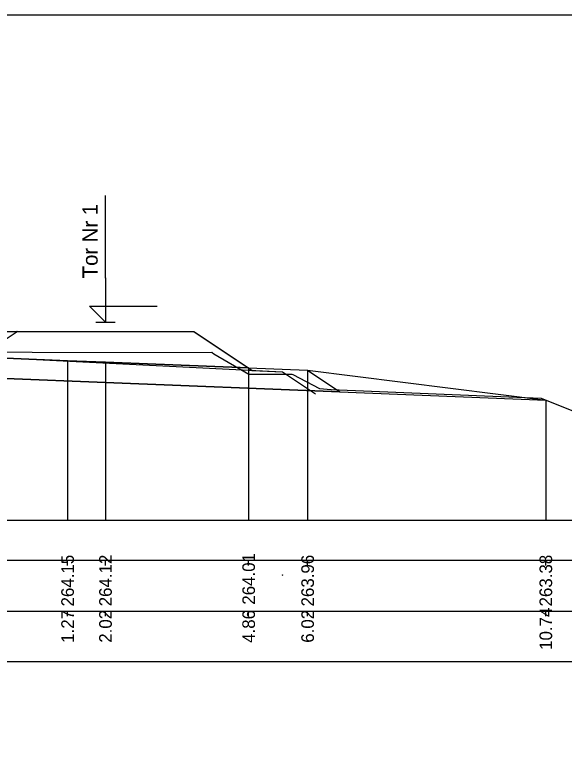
# Model space of a CAD drawing. Extents: x -1 to 65640748, y -22 to 5530284.
# Drawn here: x 2498.56 to 2509.43, y 1008.9 to 1023.44 of the extents above; entities that cross this region are included whole.
import ezdxf

# ---------------------------------------------------------------- set-up
doc = ezdxf.new("R2010")
doc.units = 0
for name, color, linetype in [('IR_cross_section', 7, 'Continuous'), ('IR_default', 7, 'Continuous'), ('TOR_PRZEK_P-komponent', 7, 'Continuous'), ('TOR_PRZEK_P-tabelka projektowane', 7, 'Continuous'), ('TOR_PRZEK_P-teren istniejacy', 7, 'Continuous'), ('TOR_PRZEK_P-tluczen+miedzytorze', 7, 'Continuous'), ('TOR_PRZEK_P-tory projektowane', 7, 'Continuous'), ('TOR_PRZEK_P-uklad odniesienia', 7, 'Continuous'), ('TOR_PRZEK_P-warstwa ochronna I', 7, 'Continuous'), ('TOR_PRZEK_P-warstwa ochronna II', 7, 'Continuous')]:
    doc.layers.add(name, color=color, linetype=linetype)

msp = doc.modelspace()

# ---------------------------------------------------------------- linework, layer by layer
msp.add_lwpolyline([(2504.353, 1016.402), (2504.991, 1015.977), (2509.066, 1015.814)])
at = {"layer": 'IR_cross_section'}
msp.add_lwpolyline([(2476.328, 1023.438), (2676.328, 1023.438), (2676.328, 994.938), (2476.328, 994.938)], close=True, dxfattribs=at)
at = {"layer": 'IR_default'}
for points in [[(2487.865, 1016.59), (2489.083, 1015.778), (2489.833, 1015.278), (2490.233, 1015.278), (2490.983, 1015.778), (2491.983, 1015.828), (2492.149, 1015.938), (2492.15, 1015.938), (2492.798, 1016.371), (2493.398, 1016.401), (2494.553, 1017.171), (2496.303, 1017.171), (2497.059, 1017.171), (2498.053, 1017.171), (2498.054, 1017.171), (2498.602, 1017.171), (2498.603, 1017.171), (2499.597, 1017.171), (2500.353, 1017.171), (2502.103, 1017.171), (2503.258, 1016.401), (2503.858, 1016.371), (2504.506, 1015.939)], [(2488.017, 1016.608), (2489.532, 1015.598), (2490.118, 1015.208), (2490.463, 1015.208), (2490.518, 1015.208), (2490.644, 1015.292), (2491.665, 1015.972), (2492.303, 1016.398), (2493.462, 1016.444), (2494.552, 1017.171), (2498.053, 1017.171), (2498.216, 1017.171), (2498.602, 1017.171), (2500.41, 1017.171), (2502.102, 1017.171), (2503.186, 1016.449), (2504.353, 1016.402), (2504.991, 1015.977), (2509.066, 1015.814)], [(2502.461, 1016.754), (2502.46, 1016.754), (2502.461, 1016.754), (2502.46, 1016.753), (2502.461, 1016.754), (2502.461, 1016.753), (2502.461, 1016.754), (2502.461, 1016.754)], [(2503.189, 1016.327), (2503.188, 1016.327), (2503.189, 1016.327), (2503.188, 1016.326), (2503.189, 1016.327), (2503.189, 1016.326), (2503.189, 1016.327), (2503.189, 1016.327)], [(2504.039, 1016.328), (2504.039, 1016.328), (2504.039, 1016.328), (2504.039, 1016.327), (2504.039, 1016.328), (2504.04, 1016.327), (2504.039, 1016.328), (2504.04, 1016.328)], [(2504.353, 1016.402), (2504.352, 1016.403), (2504.353, 1016.402), (2504.352, 1016.402), (2504.353, 1016.402), (2504.353, 1016.402), (2504.353, 1016.402), (2504.353, 1016.403)], [(2504.591, 1016.039), (2504.59, 1016.04), (2504.591, 1016.039), (2504.59, 1016.039), (2504.591, 1016.039), (2504.591, 1016.039), (2504.591, 1016.039), (2504.591, 1016.04)], [(2508.974, 1015.851), (2508.973, 1015.852), (2508.974, 1015.851), (2508.973, 1015.851), (2508.974, 1015.851), (2508.974, 1015.851), (2508.974, 1015.851), (2508.974, 1015.852)]]:
    msp.add_lwpolyline(points, dxfattribs=at)
at = {"layer": 'TOR_PRZEK_P-komponent'}
for points in [[(2493.398, 1016.401), (2494.553, 1017.171), (2498.053, 1017.171), (2498.327, 1016.988), (2498.329, 1016.988), (2498.603, 1017.171), (2502.103, 1017.171), (2503.258, 1016.401)], [(2498.602, 1017.171), (2498.601, 1017.172), (2498.602, 1017.171), (2498.601, 1017.171), (2498.602, 1017.171), (2498.602, 1017.171), (2498.602, 1017.171), (2498.602, 1017.172)]]:
    msp.add_lwpolyline(points, dxfattribs=at)
msp.add_lwpolyline([(2494.552, 1017.171), (2498.053, 1017.171), (2498.602, 1017.171), (2502.102, 1017.171), (2503.186, 1016.449), (2500.353, 1016.562), (2499.603, 1016.592), (2498.383, 1016.641), (2497.053, 1016.588), (2496.303, 1016.558), (2493.462, 1016.444), (2493.462, 1016.444)], close=True, dxfattribs=at)
at = {"layer": 'TOR_PRZEK_P-tabelka projektowane'}
for p, q in [((2499.603, 1012.538), (2499.603, 1012.638)), ((2500.353, 1012.538), (2500.353, 1012.638)), ((2503.186, 1012.538), (2503.186, 1012.638)), ((2504.353, 1012.538), (2504.353, 1012.638)), ((2509.066, 1012.538), (2509.066, 1012.638)), ((2479.528, 1011.638), (2513.328, 1011.638)), ((2499.603, 1011.538), (2499.603, 1011.638)), ((2500.353, 1011.538), (2500.353, 1011.638)), ((2503.186, 1011.538), (2503.186, 1011.638)), ((2504.353, 1011.538), (2504.353, 1011.638)), ((2509.066, 1011.538), (2509.066, 1011.638))]:
    msp.add_line(p, q, dxfattribs=at)
for points in [[(2499.603, 1016.592), (2499.603, 1013.638), (2499.603, 1013.508), (2499.603, 1013.438)], [(2500.353, 1016.562), (2500.353, 1013.638), (2500.353, 1013.508), (2500.353, 1013.438)], [(2503.186, 1016.449), (2503.186, 1013.638), (2503.186, 1013.508), (2503.186, 1013.438)], [(2504.353, 1016.402), (2504.353, 1013.638), (2504.353, 1013.508), (2504.353, 1013.438)], [(2509.066, 1015.814), (2509.066, 1013.638), (2509.066, 1013.508), (2509.066, 1013.438)]]:
    msp.add_lwpolyline(points, dxfattribs=at)
msp.add_lwpolyline([(2479.528, 1012.638), (2479.528, 1010.638), (2513.328, 1010.638), (2513.328, 1012.638)], close=True, dxfattribs=at)
at = {"layer": 'TOR_PRZEK_P-teren istniejacy'}
msp.add_lwpolyline([(2487.15, 1016.583), (2488.845, 1016.599), (2490.574, 1015.309), (2491.022, 1014.924), (2491.99, 1015.676), (2492.307, 1015.878), (2492.495, 1015.928), (2493.36, 1016.12), (2493.802, 1016.079), (2493.824, 1016.082), (2493.866, 1016.105), (2495.016, 1016.767), (2495.335, 1016.764), (2502.461, 1016.754), (2502.497, 1016.728), (2503.189, 1016.327), (2503.232, 1016.328), (2504.039, 1016.328), (2504.057, 1016.32), (2504.591, 1016.039), (2504.821, 1016.023), (2508.974, 1015.851), (2509.616, 1015.59)], dxfattribs=at)
at = {"layer": 'TOR_PRZEK_P-tluczen+miedzytorze'}
for points in [[(2498.603, 1017.171), (2498.602, 1017.172), (2498.603, 1017.171), (2498.602, 1017.171), (2498.603, 1017.171), (2498.603, 1017.171), (2498.603, 1017.171), (2498.603, 1017.172)], [(2498.603, 1017.171), (2498.602, 1017.172), (2498.603, 1017.171), (2498.602, 1017.171), (2498.603, 1017.171), (2498.603, 1017.171), (2498.603, 1017.171), (2498.603, 1017.172)], [(2499.597, 1017.171), (2499.596, 1017.172), (2499.597, 1017.171), (2499.596, 1017.171), (2499.597, 1017.171), (2499.597, 1017.171), (2499.597, 1017.171), (2499.597, 1017.172)], [(2500.353, 1017.171), (2500.352, 1017.172), (2500.353, 1017.171), (2500.352, 1017.171), (2500.353, 1017.171), (2500.353, 1017.171), (2500.353, 1017.171), (2500.353, 1017.172)], [(2502.103, 1017.171), (2502.102, 1017.172), (2502.103, 1017.171), (2502.102, 1017.171), (2502.103, 1017.171), (2502.103, 1017.171), (2502.103, 1017.171), (2502.103, 1017.172)], [(2502.103, 1017.171), (2502.102, 1017.172), (2502.103, 1017.171), (2502.102, 1017.171), (2502.103, 1017.171), (2502.103, 1017.171), (2502.103, 1017.171), (2502.103, 1017.172)], [(2499.597, 1016.584), (2499.596, 1016.585), (2499.597, 1016.584), (2499.596, 1016.584), (2499.597, 1016.584), (2499.597, 1016.584), (2499.597, 1016.584), (2499.597, 1016.585)], [(2503.258, 1016.401), (2503.257, 1016.401), (2503.258, 1016.401), (2503.257, 1016.4), (2503.258, 1016.401), (2503.258, 1016.4), (2503.258, 1016.401), (2503.258, 1016.401)], [(2503.258, 1016.401), (2503.257, 1016.401), (2503.258, 1016.401), (2503.257, 1016.4), (2503.258, 1016.401), (2503.258, 1016.4), (2503.258, 1016.401), (2503.258, 1016.401)], [(2503.853, 1012.351), (2503.852, 1012.352), (2503.853, 1012.351), (2503.852, 1012.351), (2503.853, 1012.351), (2503.853, 1012.351), (2503.853, 1012.351), (2503.853, 1012.352)], [(2503.858, 1012.351), (2503.857, 1012.352), (2503.858, 1012.351), (2503.857, 1012.351), (2503.858, 1012.351), (2503.858, 1012.351), (2503.858, 1012.351), (2503.858, 1012.352)]]:
    msp.add_lwpolyline(points, dxfattribs=at)
at = {"layer": 'TOR_PRZEK_P-tory projektowane'}
for p, q in [((2500.353, 1018.228), (2500.353, 1019.861)), ((2500.353, 1018.229), (2500.353, 1019.861)), ((2500.353, 1018.229), (2500.353, 1017.351)), ((2500.353, 1018.228), (2500.353, 1017.351)), ((2500.353, 1017.351), (2500.034, 1017.67)), ((2500.034, 1017.67), (2501.378, 1017.67)), ((2500.353, 1017.351), (2500.034, 1017.67)), ((2500.034, 1017.67), (2501.378, 1017.67)), ((2500.161, 1017.351), (2500.545, 1017.351)), ((2500.161, 1017.351), (2500.544, 1017.351))]:
    msp.add_line(p, q, dxfattribs=at)
at = {"layer": 'TOR_PRZEK_P-uklad odniesienia'}
msp.add_line((2483.328, 1013.438), (2513.328, 1013.438), dxfattribs=at)
at = {"layer": 'TOR_PRZEK_P-warstwa ochronna I'}
for points in [[(2492.15, 1015.938), (2492.798, 1016.371), (2498.327, 1016.647), (2498.329, 1016.647), (2503.858, 1016.371), (2504.506, 1015.939)], [(2503.858, 1016.371), (2503.857, 1016.371), (2503.858, 1016.371), (2503.857, 1016.37), (2503.858, 1016.371), (2503.858, 1016.37), (2503.858, 1016.371), (2503.858, 1016.371)], [(2503.858, 1016.371), (2503.857, 1016.371), (2503.858, 1016.371), (2503.857, 1016.37), (2503.858, 1016.371), (2503.858, 1016.37), (2503.858, 1016.371), (2503.858, 1016.371)], [(2503.858, 1016.371), (2503.857, 1016.371), (2503.858, 1016.371), (2503.857, 1016.37), (2503.858, 1016.371), (2503.858, 1016.37), (2503.858, 1016.371), (2503.858, 1016.371)], [(2491.664, 1015.972), (2496.303, 1016.158), (2498.383, 1016.241), (2500.353, 1016.162), (2504.991, 1015.977)], [(2504.506, 1015.939), (2504.506, 1015.939), (2504.506, 1015.939), (2504.506, 1015.938), (2504.506, 1015.939), (2504.507, 1015.938), (2504.506, 1015.939), (2504.507, 1015.939)], [(2504.506, 1015.939), (2504.506, 1015.939), (2504.506, 1015.939), (2504.506, 1015.938), (2504.506, 1015.939), (2504.507, 1015.938), (2504.506, 1015.939), (2504.507, 1015.939)]]:
    msp.add_lwpolyline(points, dxfattribs=at)
at = {"layer": 'TOR_PRZEK_P-warstwa ochronna II'}
msp.add_lwpolyline([(2488.017, 1016.608), (2490.118, 1015.208), (2490.518, 1015.208), (2492.303, 1016.398), (2496.303, 1016.558), (2497.053, 1016.588), (2498.383, 1016.641), (2499.603, 1016.592), (2500.353, 1016.562), (2503.186, 1016.449), (2504.353, 1016.402), (2509.066, 1015.814)], dxfattribs=at)
msp.add_lwpolyline([(2493.462, 1016.444), (2493.462, 1016.444), (2496.303, 1016.558), (2497.053, 1016.588), (2498.383, 1016.641), (2499.603, 1016.592), (2500.353, 1016.562), (2503.186, 1016.449), (2504.353, 1016.402), (2504.991, 1015.977), (2500.353, 1016.162), (2498.383, 1016.241), (2496.303, 1016.158), (2491.665, 1015.972), (2492.303, 1016.398)], close=True, dxfattribs=at)

# ---------------------------------------------------------------- texts
at = {"layer": 'TOR_PRZEK_P-tabelka projektowane'}
for s, p in [('264.15', (2499.728, 1011.729)), ('264.12', (2500.478, 1011.732)), ('264.01', (2503.311, 1011.764)), ('263.96', (2504.478, 1011.729)), ('263.38', (2509.191, 1011.729)), ('1.27', (2499.728, 1011.01)), ('2.02', (2500.478, 1011.011)), ('4.86', (2503.311, 1011.009)), ('6.02', (2504.478, 1011.011)), ('10.74', (2509.191, 1010.87))]:
    msp.add_text(s, height=0.25, rotation=90, dxfattribs=at).set_placement(p)
at = {"layer": 'TOR_PRZEK_P-tory projektowane'}
for p in [(2500.198, 1018.222), (2500.198, 1018.223)]:
    msp.add_text('Tor Nr 1', height=0.3, rotation=90, dxfattribs=at).set_placement(p)

doc.saveas('drawing.dxf')
